(* Logix 5000 project; controller AMCI_3202_generic_sample_RSLogix_V28 vendor 1 type 14 code 92 rev 28.11; software revision 28.00 *)

TASK MainTask (continuous, watchdog 500 ms) : MainProgram

MODULES
   Local : vendor 1 type 14 code 92 (ICP 0, rev 28.11)
      AMCI_3202 : vendor 1 type 0 code 15 (ICP 3, rev 1.1, Output RPI 5 ms)
           Local:3:O.Data[0]   // AMCI 3202 module channel 1 command word
           Local:3:O.Data[8]   // AMCI 3202 module channel 2 command word
           Local:3:I.Data[0].0   // Set when 3202 channel 1 CW motion occurring
           Local:3:I.Data[0].1   // set when 3202 channel 1 CCW motion is occurring
           Local:3:I.Data[0].7   // AMCI 3202 channel 1 move complete bit
           Local:3:I.Data[1]   // AMCI 3202 ch 1 current position data
           Local:3:I.Data[0].10   // AMCI 3202 ch 1 position invalid bit
           Local:3:I.Data[0].13   // Set when AMCI 3202 ch 1 has a configuration error
           Local:3:I.Data[0].31   // AMCI 3202 ch 1 mode bit 1=config mode 0=command mode
           Local:3:I.Data[0].28   // Set when AMCI 3202 ch 1 is disabled
END_MODULES

VAR_GLOBAL   (* controller tags *)
   blend_data_3202_ch1 : DINT[52];
        [13]   // Segment 4 length
        [12]   // Segment 3 Acceleration or Deceleration
        [11]   // Segment 3 speed
        [15]   // Segment 4 Acceleration or Deceleration
        [9]   // Segment 2 Acceleration or Deceleration
        [3]   // Final Segment's Deceleration Value and Type
        [1]   // Number of Segments
        [17]   // Segment 5 speed
        [5]   // Segment 1 speed
        [7]   // Segment 2 length
        [10]   // Segment 3 length
        [14]   // Segment 4 speed
        [16]   // Segment 5 length
        [18]   // Segment 5 Acceleraiton or Deceleration
        [0]   // channel number (1 or 2)
        [2]   // Acceleration Type
        [4]   // Segment 1 length
        [6]   // Segment 1 Acceleration or Deceleration
        [8]   // Segment 2 speed
   blend_data_3202_ch2 : DINT[52];
        [4]   // Segment 1 length
        [14]   // Segment 4 speed
        [6]   // Segment 1 Acceleration or Deceleration
        [17]   // Segment 5 speed
        [11]   // Segment 3 speed
        [15]   // Segment 4 Acceleration or Deceleration
        [1]   // Number of Segments
        [13]   // Segment 4 length
        [3]   // Final Segment's Deceleration Value and Type
        [16]   // Segment 5 length
        [5]   // Segment 1 speed
        [9]   // Segment 2 Acceleration or Deceleration
        [0]   // channel number (1 or 2)
        [7]   // Segment 2 length
        [12]   // Segment 3 Acceleration or Deceleration
        [2]   // Acceleration Type
        [10]   // Segment 3 length
        [18]   // Segment 5 Acceleraiton or Deceleration
        [8]   // Segment 2 speed
   blend_message_3202_ch1 : MESSAGE;
        .DN   // set when blend data has been programmed
        MessageParameters(ServiceCode := 16#004c, LocalElement := blend_data_3202_ch1[0], ...)
   blend_message_3202_ch2 : MESSAGE;
        .DN   // set when blend data has been programmed
        MessageParameters(ServiceCode := 16#004c, LocalElement := blend_data_3202_ch2[0], ...)
   blend_run_3202_ch1 : DINT[8] := ([0] := 4096);
        [0]   // command word to run blend profile CW
   blend_run_3202_ch2 : DINT[8] := ([0] := 4096);
        [0]   // command word to run blend profile CW
   buffered_3202_data : DINT[16];
        [8].0   // set when AMCI 3202 ch 2 CW motion is occurring
        [8].31   // AMCI 3202 ch 2 mode bit 1=config mode 0=command mode
        [0].0   // set when AMCI 3202 ch 1 CW motion is occurring
        [0].1   // set when AMCI 3202 ch 1 CCW motion is occurring
        [0].7   // AMCI 3202 ch 1 move complete bit
        [8].13   // set when AMCI 3202 ch 2 has a configuration error
        [8].1   // set when AMCI 3202 ch 2 CCW motion is occurring
        [0].28   // set when AMCI 3202 ch 1 is disabled
        [8].28   // set when AMCI 3202 ch 2 is disabled
        [0].10   // AMCI 3202 ch 1 position invalid bit
        [0].13   // set when AMCI 3202 ch 1 has a configuration error
        [0].31   // AMCI 3202 ch 1 mode bit 1=config mode 0=command mode
   CCW_manual_move_3202_ch1 : DINT[8] := ([0] := 256, [2] := 2200, [3] := 10000, [4] := 10000);
   CCW_manual_move_3202_ch2 : DINT[8] := ([0] := 256, [2] := 2200, [3] := 10000, [4] := 10000);
   ch1_manual_move_occurring_CCW : BOOL;
   ch1_manual_move_occurring_CW : BOOL;
   ch2_manual_move_occurring_CCW : BOOL;
   ch2_manual_move_occurring_CW2 : BOOL;
   comment : INT;
        .1   // comment coil for version rung
   config_3202_ch1 : DINT[8] := ([0] := -2143419330, [1] := 100);
        [1]   // starting speed
        [0]   // configuration word
   config_3202_ch2 : DINT[8] := ([0] := -2143419330, [1] := 100);
        [1]   // starting speed
        [0]   // configuration word
   CW_manual_move_3202_ch1 : DINT[8] := ([0] := 128, [2] := 1500, [3] := 10000, [4] := 10000);
   CW_manual_move_3202_ch2 : DINT[8] := ([0] := 128, [2] := 1500, [3] := 10000, [4] := 10000);
   Home_CW_3202_ch1 : DINT[8] := ([0] := 32, [2] := 1000, [3] := 10000, [4] := 10000);
   Home_CW_3202_ch2 : DINT[8] := ([0] := 32, [2] := 1000, [3] := 10000, [4] := 10000);
   one_shot_1 : BOOL;
   one_shot_2 : BOOL;
   one_shot_3 : BOOL;
   one_shot_4 : BOOL;
   preset_3202_ch1 : DINT[8] := ([0] := 512);
        [0]   // preset current position command word
   preset_3202_ch2 : DINT[8] := ([0] := 512);
        [0]   // preset current position command word
   Relative_move_3202_ch1 : DINT[8] := ([0] := 2, [1] := 5000, [2] := 2000, [3] := 10000, [4] := 10000);
        [4]   // deceleration in pulses/sec/sec
        [3]   // acceleration in pulses/sec/sec
        [0]   // relative move command word
        [1]   // distance in pulses
        [2]   // speed in pulses/sec
   Relative_move_3202_ch2 : DINT[8] := ([0] := 2, [1] := 5000, [2] := 2000, [3] := 10000, [4] := 10000);
        [3]   // acceleration in pulses/sec/sec
        [4]   // deceleration in pulses/sec/sec
        [0]   // relative move command word
        [1]   // distance in pulses
        [2]   // speed in pulses/sec
   Reset_errors_3202 : DINT[8] := ([0] := 2048);
   run_3202_ch1 : INT;   // 1=Relative move 2=CW Manual Move 3=CCW Manual Move 4=Reset Errors 5=Home CW 6=Preset 7=Program Blend 8=Run Blend CW
   run_3202_ch2 : INT;   // 1=Relative move 2=CW Manual Move 3=CCW Manual Move 4=Reset Errors 5=Home CW 6=Preset 7=Program Blend 8=Run Blend CW
END_VAR

PROGRAM MainProgram   (* main routine MainRoutine *)

ROUTINE channel_1_3202   (* ladder *)
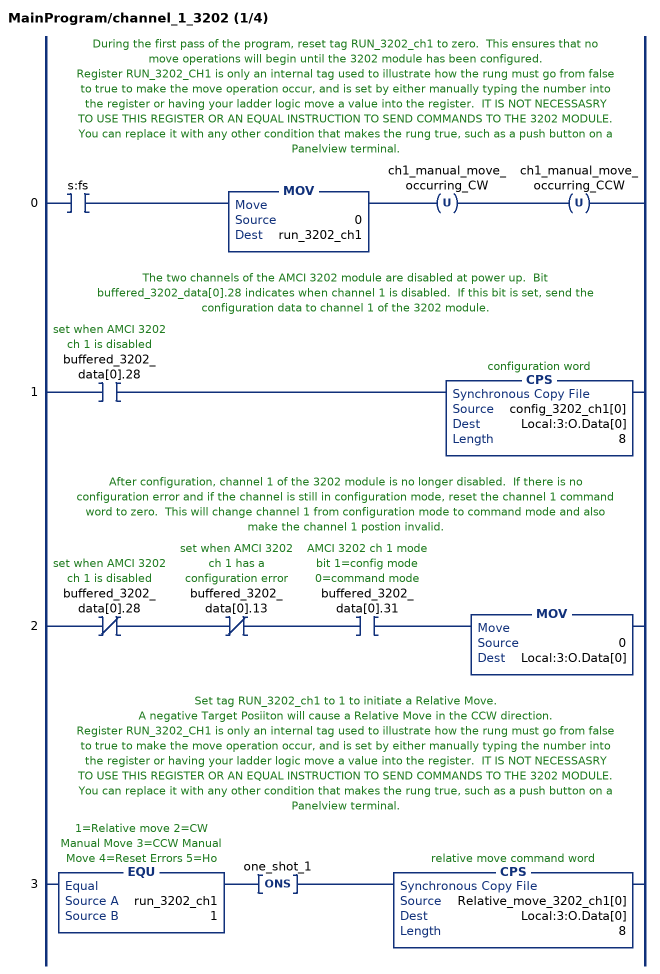
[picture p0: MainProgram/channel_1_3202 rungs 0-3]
   // During the first pass of the program, reset tag RUN_3202_ch1 to zero.  This ensures that no move operations will begin until the 3202 module has been configured.
   // Register RUN_3202_CH1 is only an internal tag used to illustrate how the rung must go from false to true to make the move operation occur, and is set by either manually typing the number into the register or having your ladder logic move a value into the register.  IT IS NOT NECESSASRY TO USE THIS REGISTER OR AN EQUAL INSTRUCTION TO SEND COMMANDS TO THE 3202 MODULE.  You can replace it with any other condition that makes the rung true, such as a push button on a Panelview terminal.
   0: XIC(s:fs)MOV(0,run_3202_ch1)OTU(ch1_manual_move_occurring_CW)OTU(ch1_manual_move_occurring_CCW);
   // The two channels of the AMCI 3202 module are disabled at power up.  Bit buffered_3202_data[0].28 indicates when channel 1 is disabled.  If this bit is set, send the configuration data to channel 1 of the 3202 module.
   1: XIC(buffered_3202_data[0].28)CPS(config_3202_ch1[0],Local:3:O.Data[0],8);
   // After configuration, channel 1 of the 3202 module is no longer disabled.  If there is no configuration error and if the channel is still in configuration mode, reset the channel 1 command word to zero.  This will change channel 1 from configuration mode to command mode and also make the channel 1 postion invalid.
   2: XIO(buffered_3202_data[0].28)XIO(buffered_3202_data[0].13)XIC(buffered_3202_data[0].31)MOV(0,Local:3:O.Data[0]);
   // Set tag RUN_3202_ch1 to 1 to initiate a Relative Move.
   // A negative Target Posiiton will cause a Relative Move in the CCW direction.
   // Register RUN_3202_CH1 is only an internal tag used to illustrate how the rung must go from false to true to make the move operation occur, and is set by either manually typing the number into the register or having your ladder logic move a value into the register.  IT IS NOT NECESSASRY TO USE THIS REGISTER OR AN EQUAL INSTRUCTION TO SEND COMMANDS TO THE 3202 MODULE.  You can replace it with any other condition that makes the rung true, such as a push button on a Panelview terminal.
   3: EQU(run_3202_ch1,1)ONS(one_shot_1)CPS(Relative_move_3202_ch1[0],Local:3:O.Data[0],8);
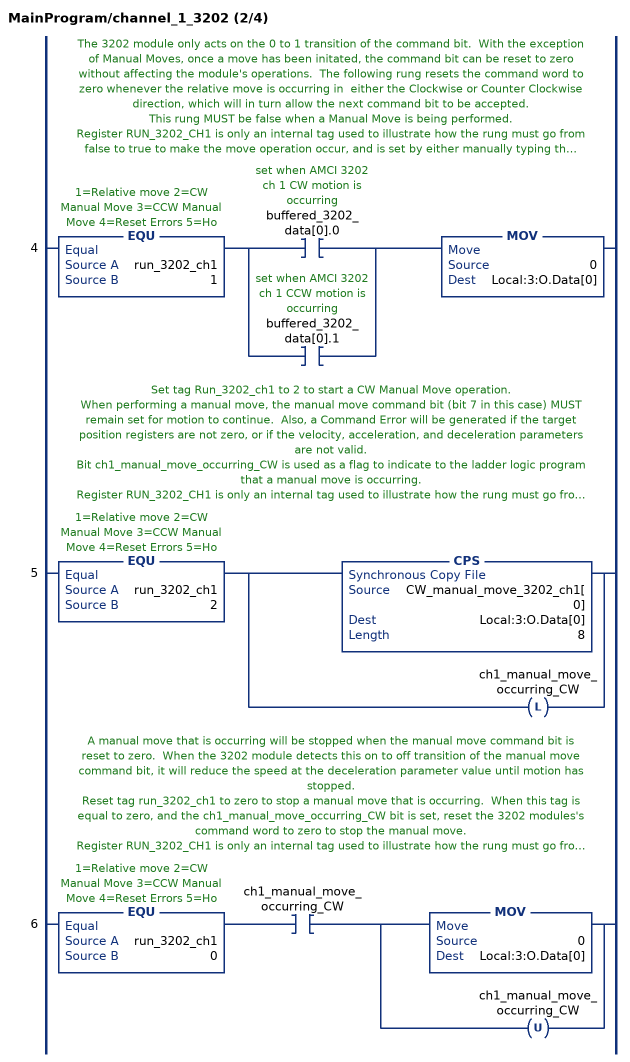
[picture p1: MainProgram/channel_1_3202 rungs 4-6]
   // The 3202 module only acts on the 0 to 1 transition of the command bit.  With the exception of Manual Moves, once a move has been initated, the command bit can be reset to zero without affecting the module's operations.  The following rung resets the command word to zero whenever the relative move is occurring in  either the Clockwise or Counter Clockwise direction, which will in turn allow the next command bit to be accepted.
   // This rung MUST be false when a Manual Move is being performed.
   // Register RUN_3202_CH1 is only an internal tag used to illustrate how the rung must go from false to true to make the move operation occur, and is set by either manually typing the number into the register or having your ladder logic move a value into the register.  IT IS NOT NECESSASRY TO USE THIS REGISTER OR AN EQUAL INSTRUCTION TO SEND COMMANDS TO THE 3202 MODULE.  You can replace it with any other condition that makes the rung true, such as a push button on a Panelview terminal.
   4: EQU(run_3202_ch1,1)[XIC(buffered_3202_data[0].0) ,XIC(buffered_3202_data[0].1) ]MOV(0,Local:3:O.Data[0]);
   // Set tag Run_3202_ch1 to 2 to start a CW Manual Move operation.
   // When performing a manual move, the manual move command bit (bit 7 in this case) MUST remain set for motion to continue.  Also, a Command Error will be generated if the target position registers are not zero, or if the velocity, acceleration, and deceleration parameters are not valid.
   // Bit ch1_manual_move_occurring_CW is used as a flag to indicate to the ladder logic program that a manual move is occurring.
   // Register RUN_3202_CH1 is only an internal tag used to illustrate how the rung must go from false to true to make the move operation occur, and is set by either manually typing the number into the register or having your ladder logic move a value into the register.  IT IS NOT NECESSASRY TO USE THIS REGISTER OR AN EQUAL INSTRUCTION TO SEND COMMANDS TO THE 3202 MODULE.  You can replace it with any other condition that makes the rung true, such as a push button on a Panelview terminal.
   5: EQU(run_3202_ch1,2)[CPS(CW_manual_move_3202_ch1[0],Local:3:O.Data[0],8) ,OTL(ch1_manual_move_occurring_CW) ];
   // A manual move that is occurring will be stopped when the manual move command bit is reset to zero.  When the 3202 module detects this on to off transition of the manual move command bit, it will reduce the speed at the deceleration parameter value until motion has stopped.
   // Reset tag run_3202_ch1 to zero to stop a manual move that is occurring.  When this tag is equal to zero, and the ch1_manual_move_occurring_CW bit is set, reset the 3202 modules's command word to zero to stop the manual move.
   // Register RUN_3202_CH1 is only an internal tag used to illustrate how the rung must go from false to true to make the move operation occur, and is set by either manually typing the number into the register or having your ladder logic move a value into the register.  IT IS NOT NECESSASRY TO USE THIS REGISTER OR AN EQUAL INSTRUCTION TO SEND COMMANDS TO THE 3202 MODULE.  You can replace it with any other condition that makes the rung true, such as a push button on a Panelview terminal.
   6: EQU(run_3202_ch1,0)XIC(ch1_manual_move_occurring_CW)[MOV(0,Local:3:O.Data[0]) ,OTU(ch1_manual_move_occurring_CW) ];
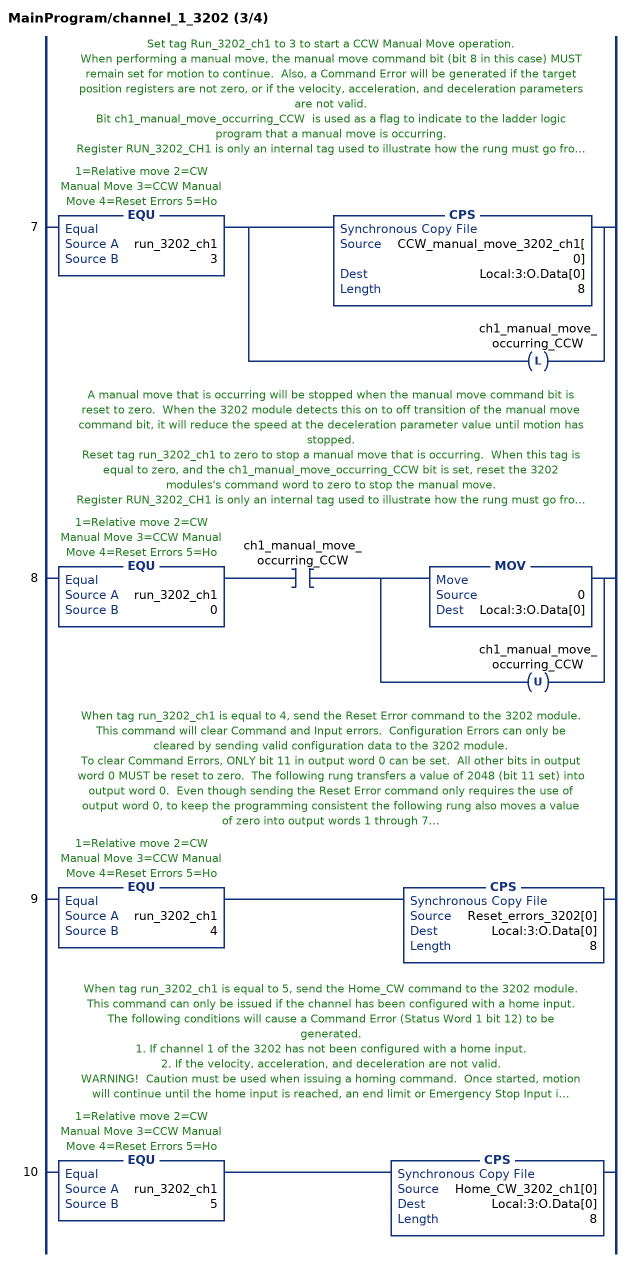
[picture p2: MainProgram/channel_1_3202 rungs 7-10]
   // Set tag Run_3202_ch1 to 3 to start a CCW Manual Move operation.
   // When performing a manual move, the manual move command bit (bit 8 in this case) MUST remain set for motion to continue.  Also, a Command Error will be generated if the target position registers are not zero, or if the velocity, acceleration, and deceleration parameters are not valid.
   // Bit ch1_manual_move_occurring_CCW  is used as a flag to indicate to the ladder logic program that a manual move is occurring.
   // Register RUN_3202_CH1 is only an internal tag used to illustrate how the rung must go from false to true to make the move operation occur, and is set by either manually typing the number into the register or having your ladder logic move a value into the register.  IT IS NOT NECESSASRY TO USE THIS REGISTER OR AN EQUAL INSTRUCTION TO SEND COMMANDS TO THE 3202 MODULE.  You can replace it with any other condition that makes the rung true, such as a push button on a Panelview terminal.
   7: EQU(run_3202_ch1,3)[CPS(CCW_manual_move_3202_ch1[0],Local:3:O.Data[0],8) ,OTL(ch1_manual_move_occurring_CCW) ];
   // A manual move that is occurring will be stopped when the manual move command bit is reset to zero.  When the 3202 module detects this on to off transition of the manual move command bit, it will reduce the speed at the deceleration parameter value until motion has stopped.
   // Reset tag run_3202_ch1 to zero to stop a manual move that is occurring.  When this tag is equal to zero, and the ch1_manual_move_occurring_CCW bit is set, reset the 3202 modules's command word to zero to stop the manual move.
   // Register RUN_3202_CH1 is only an internal tag used to illustrate how the rung must go from false to true to make the move operation occur, and is set by either manually typing the number into the register or having your ladder logic move a value into the register.  IT IS NOT NECESSASRY TO USE THIS REGISTER OR AN EQUAL INSTRUCTION TO SEND COMMANDS TO THE 3202 MODULE.  You can replace it with any other condition that makes the rung true, such as a push button on a Panelview terminal.
   8: EQU(run_3202_ch1,0)XIC(ch1_manual_move_occurring_CCW)[MOV(0,Local:3:O.Data[0]) ,OTU(ch1_manual_move_occurring_CCW) ];
   // When tag run_3202_ch1 is equal to 4, send the Reset Error command to the 3202 module.  This command will clear Command and Input errors.  Configuration Errors can only be cleared by sending valid configuration data to the 3202 module.
   // To clear Command Errors, ONLY bit 11 in output word 0 can be set.  All other bits in output word 0 MUST be reset to zero.  The following rung transfers a value of 2048 (bit 11 set) into output word 0.  Even though sending the Reset Error command only requires the use of output word 0, to keep the programming consistent the following rung also moves a value of zero into output words 1 through 7.
   // Register RUN_3202_CH1 is only an internal tag used to illustrate how the rung must go from false to true to make the move operation occur, and is set by either manually typing the number into the register or having your ladder logic move a value into the register.  IT IS NOT NECESSASRY TO USE THIS REGISTER OR AN EQUAL INSTRUCTION TO SEND COMMANDS TO THE 3202 MODULE.  You can replace it with any other condition that makes the rung true, such as a push button on a Panelview terminal.
   9: EQU(run_3202_ch1,4)CPS(Reset_errors_3202[0],Local:3:O.Data[0],8);
   // When tag run_3202_ch1 is equal to 5, send the Home_CW command to the 3202 module.  This command can only be issued if the channel has been configured with a home input.  The following conditions will cause a Command Error (Status Word 1 bit 12) to be generated.
   // 1. If channel 1 of the 3202 has not been configured with a home input.
   // 2. If the velocity, acceleration, and deceleration are not valid.
   // WARNING!  Caution must be used when issuing a homing command.  Once started, motion will continue until the home input is reached, an end limit or Emergency Stop Input in reached, or the Immediate Stop Command is issued.  Resetting the command word to zero WILL NOT STOP a home operation.
   // Register RUN_3202_CH1 is only an internal tag used to illustrate how the rung must go from false to true to make the move operation occur, and is set by either manually typing the number into the register or having your ladder logic move a value into the register.  IT IS NOT NECESSASRY TO USE THIS REGISTER OR AN EQUAL INSTRUCTION TO SEND COMMANDS TO THE 3202 MODULE.  You can replace it with any other condition that makes the rung true, such as a push button on a Panelview terminal.
   10: EQU(run_3202_ch1,5)CPS(Home_CW_3202_ch1[0],Local:3:O.Data[0],8);
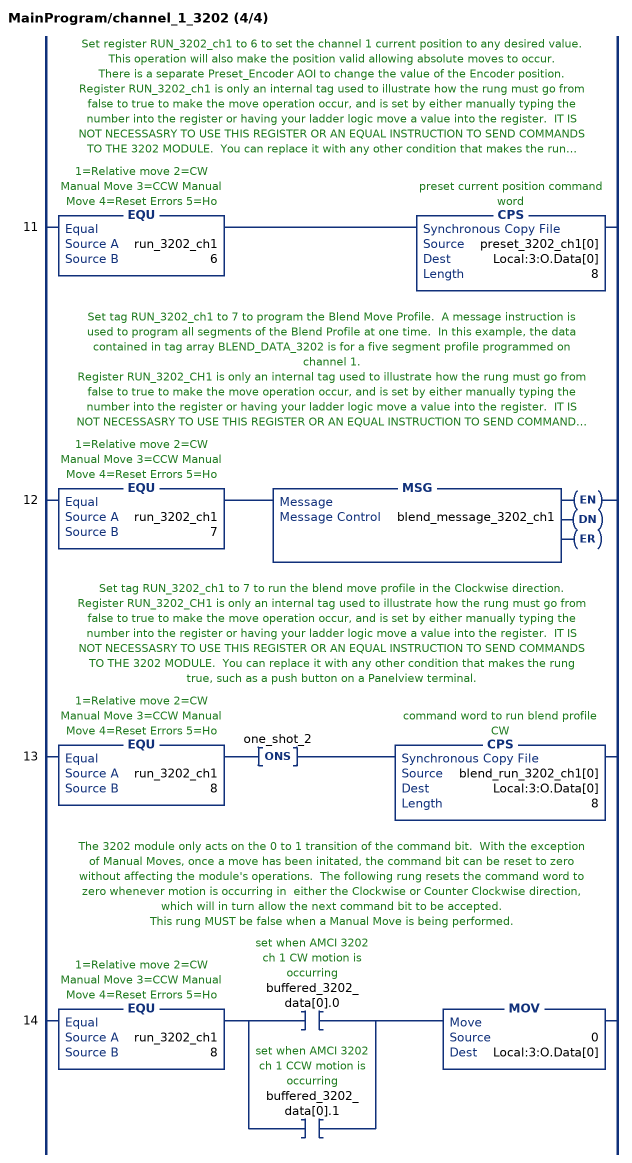
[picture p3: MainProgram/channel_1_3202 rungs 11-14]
   // Set register RUN_3202_ch1 to 6 to set the channel 1 current position to any desired value.  This operation will also make the position valid allowing absolute moves to occur.
   // There is a separate Preset_Encoder AOI to change the value of the Encoder position.
   // Register RUN_3202_ch1 is only an internal tag used to illustrate how the rung must go from false to true to make the move operation occur, and is set by either manually typing the number into the register or having your ladder logic move a value into the register.  IT IS NOT NECESSASRY TO USE THIS REGISTER OR AN EQUAL INSTRUCTION TO SEND COMMANDS TO THE 3202 MODULE.  You can replace it with any other condition that makes the rung true, such as a push button on a Panelview terminal.
   11: EQU(run_3202_ch1,6)CPS(preset_3202_ch1[0],Local:3:O.Data[0],8);
   // Set tag RUN_3202_ch1 to 7 to program the Blend Move Profile.  A message instruction is used to program all segments of the Blend Profile at one time.  In this example, the data contained in tag array BLEND_DATA_3202 is for a five segment profile programmed on channel 1.
   // Register RUN_3202_CH1 is only an internal tag used to illustrate how the rung must go from false to true to make the move operation occur, and is set by either manually typing the number into the register or having your ladder logic move a value into the register.  IT IS NOT NECESSASRY TO USE THIS REGISTER OR AN EQUAL INSTRUCTION TO SEND COMMANDS TO THE 3202 MODULE.  You can replace it with any other condition that makes the rung true, such as a push button on a Panelview terminal.
   12: EQU(run_3202_ch1,7)MSG(blend_message_3202_ch1);
   // Set tag RUN_3202_ch1 to 7 to run the blend move profile in the Clockwise direction.
   // Register RUN_3202_CH1 is only an internal tag used to illustrate how the rung must go from false to true to make the move operation occur, and is set by either manually typing the number into the register or having your ladder logic move a value into the register.  IT IS NOT NECESSASRY TO USE THIS REGISTER OR AN EQUAL INSTRUCTION TO SEND COMMANDS TO THE 3202 MODULE.  You can replace it with any other condition that makes the rung true, such as a push button on a Panelview terminal.
   13: EQU(run_3202_ch1,8)ONS(one_shot_2)CPS(blend_run_3202_ch1[0],Local:3:O.Data[0],8);
   // The 3202 module only acts on the 0 to 1 transition of the command bit.  With the exception of Manual Moves, once a move has been initated, the command bit can be reset to zero without affecting the module's operations.  The following rung resets the command word to zero whenever motion is occurring in  either the Clockwise or Counter Clockwise direction, which will in turn allow the next command bit to be accepted.
   // This rung MUST be false when a Manual Move is being performed.
   14: EQU(run_3202_ch1,8)[XIC(buffered_3202_data[0].0) ,XIC(buffered_3202_data[0].1) ]MOV(0,Local:3:O.Data[0]);
END_ROUTINE

ROUTINE channel_2_3202   (* ladder *)
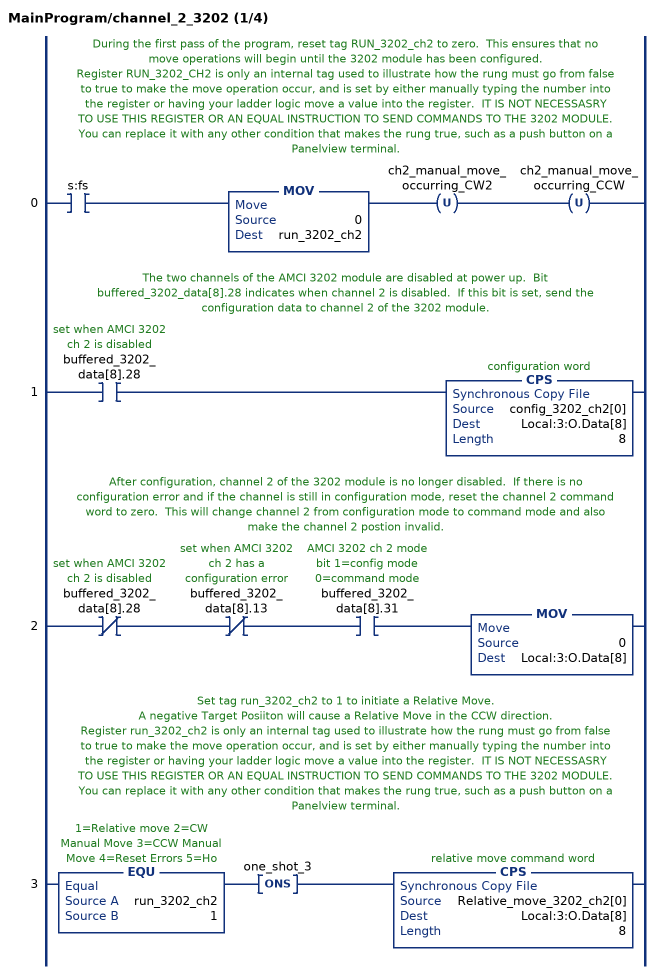
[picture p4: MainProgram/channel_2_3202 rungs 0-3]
   // During the first pass of the program, reset tag RUN_3202_ch2 to zero.  This ensures that no move operations will begin until the 3202 module has been configured.
   // Register RUN_3202_CH2 is only an internal tag used to illustrate how the rung must go from false to true to make the move operation occur, and is set by either manually typing the number into the register or having your ladder logic move a value into the register.  IT IS NOT NECESSASRY TO USE THIS REGISTER OR AN EQUAL INSTRUCTION TO SEND COMMANDS TO THE 3202 MODULE.  You can replace it with any other condition that makes the rung true, such as a push button on a Panelview terminal.
   0: XIC(s:fs)MOV(0,run_3202_ch2)OTU(ch2_manual_move_occurring_CW2)OTU(ch2_manual_move_occurring_CCW);
   // The two channels of the AMCI 3202 module are disabled at power up.  Bit buffered_3202_data[8].28 indicates when channel 2 is disabled.  If this bit is set, send the configuration data to channel 2 of the 3202 module.
   1: XIC(buffered_3202_data[8].28)CPS(config_3202_ch2[0],Local:3:O.Data[8],8);
   // After configuration, channel 2 of the 3202 module is no longer disabled.  If there is no configuration error and if the channel is still in configuration mode, reset the channel 2 command word to zero.  This will change channel 2 from configuration mode to command mode and also make the channel 2 postion invalid.
   2: XIO(buffered_3202_data[8].28)XIO(buffered_3202_data[8].13)XIC(buffered_3202_data[8].31)MOV(0,Local:3:O.Data[8]);
   // Set tag run_3202_ch2 to 1 to initiate a Relative Move.
   // A negative Target Posiiton will cause a Relative Move in the CCW direction.
   // Register run_3202_ch2 is only an internal tag used to illustrate how the rung must go from false to true to make the move operation occur, and is set by either manually typing the number into the register or having your ladder logic move a value into the register.  IT IS NOT NECESSASRY TO USE THIS REGISTER OR AN EQUAL INSTRUCTION TO SEND COMMANDS TO THE 3202 MODULE.  You can replace it with any other condition that makes the rung true, such as a push button on a Panelview terminal.
   3: EQU(run_3202_ch2,1)ONS(one_shot_3)CPS(Relative_move_3202_ch2[0],Local:3:O.Data[8],8);
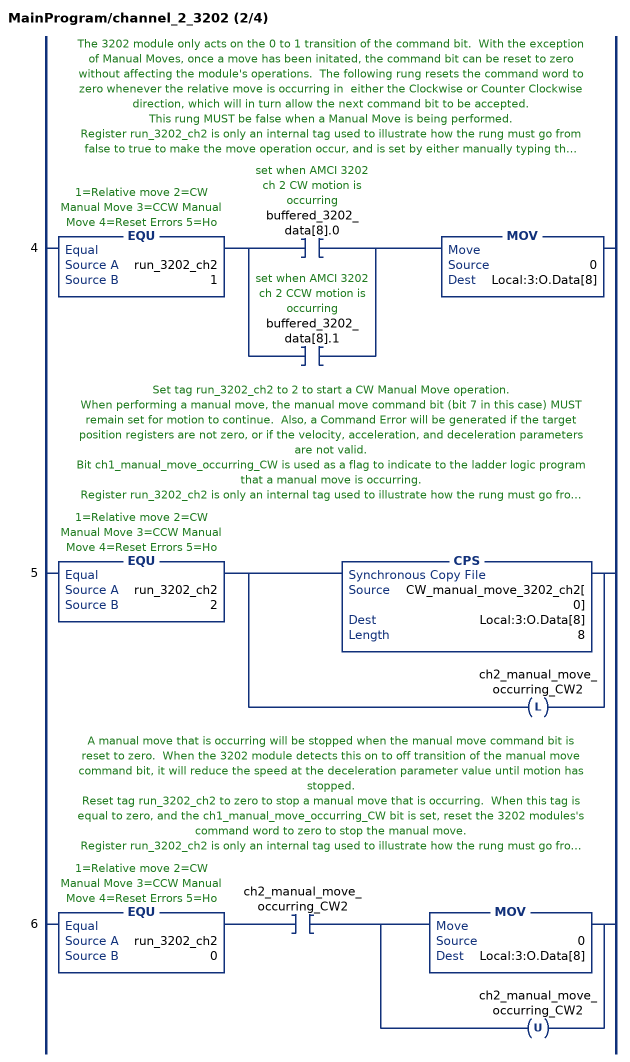
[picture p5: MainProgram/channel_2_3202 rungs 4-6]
   // The 3202 module only acts on the 0 to 1 transition of the command bit.  With the exception of Manual Moves, once a move has been initated, the command bit can be reset to zero without affecting the module's operations.  The following rung resets the command word to zero whenever the relative move is occurring in  either the Clockwise or Counter Clockwise direction, which will in turn allow the next command bit to be accepted.
   // This rung MUST be false when a Manual Move is being performed.
   // Register run_3202_ch2 is only an internal tag used to illustrate how the rung must go from false to true to make the move operation occur, and is set by either manually typing the number into the register or having your ladder logic move a value into the register.  IT IS NOT NECESSASRY TO USE THIS REGISTER OR AN EQUAL INSTRUCTION TO SEND COMMANDS TO THE 3202 MODULE.  You can replace it with any other condition that makes the rung true, such as a push button on a Panelview terminal.
   4: EQU(run_3202_ch2,1)[XIC(buffered_3202_data[8].0) ,XIC(buffered_3202_data[8].1) ]MOV(0,Local:3:O.Data[8]);
   // Set tag run_3202_ch2 to 2 to start a CW Manual Move operation.
   // When performing a manual move, the manual move command bit (bit 7 in this case) MUST remain set for motion to continue.  Also, a Command Error will be generated if the target position registers are not zero, or if the velocity, acceleration, and deceleration parameters are not valid.
   // Bit ch1_manual_move_occurring_CW is used as a flag to indicate to the ladder logic program that a manual move is occurring.
   // Register run_3202_ch2 is only an internal tag used to illustrate how the rung must go from false to true to make the move operation occur, and is set by either manually typing the number into the register or having your ladder logic move a value into the register.  IT IS NOT NECESSASRY TO USE THIS REGISTER OR AN EQUAL INSTRUCTION TO SEND COMMANDS TO THE 3202 MODULE.  You can replace it with any other condition that makes the rung true, such as a push button on a Panelview terminal.
   5: EQU(run_3202_ch2,2)[CPS(CW_manual_move_3202_ch2[0],Local:3:O.Data[8],8) ,OTL(ch2_manual_move_occurring_CW2) ];
   // A manual move that is occurring will be stopped when the manual move command bit is reset to zero.  When the 3202 module detects this on to off transition of the manual move command bit, it will reduce the speed at the deceleration parameter value until motion has stopped.
   // Reset tag run_3202_ch2 to zero to stop a manual move that is occurring.  When this tag is equal to zero, and the ch1_manual_move_occurring_CW bit is set, reset the 3202 modules's command word to zero to stop the manual move.
   // Register run_3202_ch2 is only an internal tag used to illustrate how the rung must go from false to true to make the move operation occur, and is set by either manually typing the number into the register or having your ladder logic move a value into the register.  IT IS NOT NECESSASRY TO USE THIS REGISTER OR AN EQUAL INSTRUCTION TO SEND COMMANDS TO THE 3202 MODULE.  You can replace it with any other condition that makes the rung true, such as a push button on a Panelview terminal.
   6: EQU(run_3202_ch2,0)XIC(ch2_manual_move_occurring_CW2)[MOV(0,Local:3:O.Data[8]) ,OTU(ch2_manual_move_occurring_CW2) ];
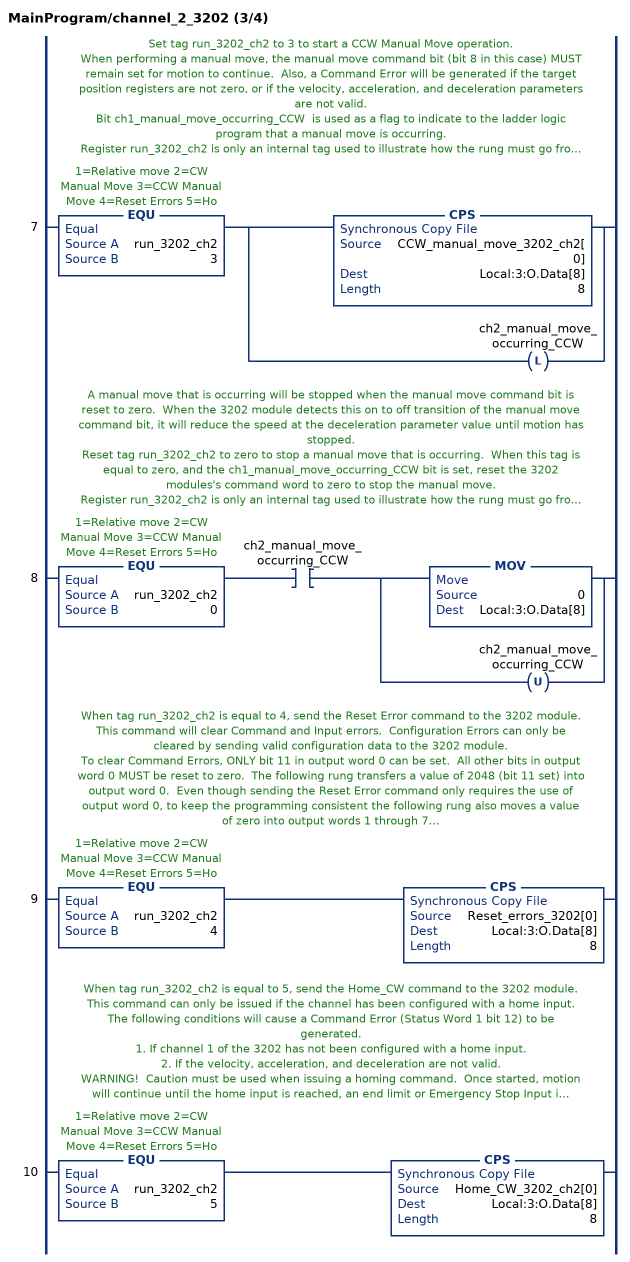
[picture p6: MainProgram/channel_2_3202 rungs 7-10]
   // Set tag run_3202_ch2 to 3 to start a CCW Manual Move operation.
   // When performing a manual move, the manual move command bit (bit 8 in this case) MUST remain set for motion to continue.  Also, a Command Error will be generated if the target position registers are not zero, or if the velocity, acceleration, and deceleration parameters are not valid.
   // Bit ch1_manual_move_occurring_CCW  is used as a flag to indicate to the ladder logic program that a manual move is occurring.
   // Register run_3202_ch2 is only an internal tag used to illustrate how the rung must go from false to true to make the move operation occur, and is set by either manually typing the number into the register or having your ladder logic move a value into the register.  IT IS NOT NECESSASRY TO USE THIS REGISTER OR AN EQUAL INSTRUCTION TO SEND COMMANDS TO THE 3202 MODULE.  You can replace it with any other condition that makes the rung true, such as a push button on a Panelview terminal.
   7: EQU(run_3202_ch2,3)[CPS(CCW_manual_move_3202_ch2[0],Local:3:O.Data[8],8) ,OTL(ch2_manual_move_occurring_CCW) ];
   // A manual move that is occurring will be stopped when the manual move command bit is reset to zero.  When the 3202 module detects this on to off transition of the manual move command bit, it will reduce the speed at the deceleration parameter value until motion has stopped.
   // Reset tag run_3202_ch2 to zero to stop a manual move that is occurring.  When this tag is equal to zero, and the ch1_manual_move_occurring_CCW bit is set, reset the 3202 modules's command word to zero to stop the manual move.
   // Register run_3202_ch2 is only an internal tag used to illustrate how the rung must go from false to true to make the move operation occur, and is set by either manually typing the number into the register or having your ladder logic move a value into the register.  IT IS NOT NECESSASRY TO USE THIS REGISTER OR AN EQUAL INSTRUCTION TO SEND COMMANDS TO THE 3202 MODULE.  You can replace it with any other condition that makes the rung true, such as a push button on a Panelview terminal.
   8: EQU(run_3202_ch2,0)XIC(ch2_manual_move_occurring_CCW)[MOV(0,Local:3:O.Data[8]) ,OTU(ch2_manual_move_occurring_CCW) ];
   // When tag run_3202_ch2 is equal to 4, send the Reset Error command to the 3202 module.  This command will clear Command and Input errors.  Configuration Errors can only be cleared by sending valid configuration data to the 3202 module.
   // To clear Command Errors, ONLY bit 11 in output word 0 can be set.  All other bits in output word 0 MUST be reset to zero.  The following rung transfers a value of 2048 (bit 11 set) into output word 0.  Even though sending the Reset Error command only requires the use of output word 0, to keep the programming consistent the following rung also moves a value of zero into output words 1 through 7.
   // Register run_3202_ch2 is only an internal tag used to illustrate how the rung must go from false to true to make the move operation occur, and is set by either manually typing the number into the register or having your ladder logic move a value into the register.  IT IS NOT NECESSASRY TO USE THIS REGISTER OR AN EQUAL INSTRUCTION TO SEND COMMANDS TO THE 3202 MODULE.  You can replace it with any other condition that makes the rung true, such as a push button on a Panelview terminal.
   9: EQU(run_3202_ch2,4)CPS(Reset_errors_3202[0],Local:3:O.Data[8],8);
   // When tag run_3202_ch2 is equal to 5, send the Home_CW command to the 3202 module.  This command can only be issued if the channel has been configured with a home input.  The following conditions will cause a Command Error (Status Word 1 bit 12) to be generated.
   // 1. If channel 1 of the 3202 has not been configured with a home input.
   // 2. If the velocity, acceleration, and deceleration are not valid.
   // WARNING!  Caution must be used when issuing a homing command.  Once started, motion will continue until the home input is reached, an end limit or Emergency Stop Input in reached, or the Immediate Stop Command is issued.  Resetting the command word to zero WILL NOT STOP a home operation.
   // Register run_3202_ch2 is only an internal tag used to illustrate how the rung must go from false to true to make the move operation occur, and is set by either manually typing the number into the register or having your ladder logic move a value into the register.  IT IS NOT NECESSASRY TO USE THIS REGISTER OR AN EQUAL INSTRUCTION TO SEND COMMANDS TO THE 3202 MODULE.  You can replace it with any other condition that makes the rung true, such as a push button on a Panelview terminal.
   10: EQU(run_3202_ch2,5)CPS(Home_CW_3202_ch2[0],Local:3:O.Data[8],8);
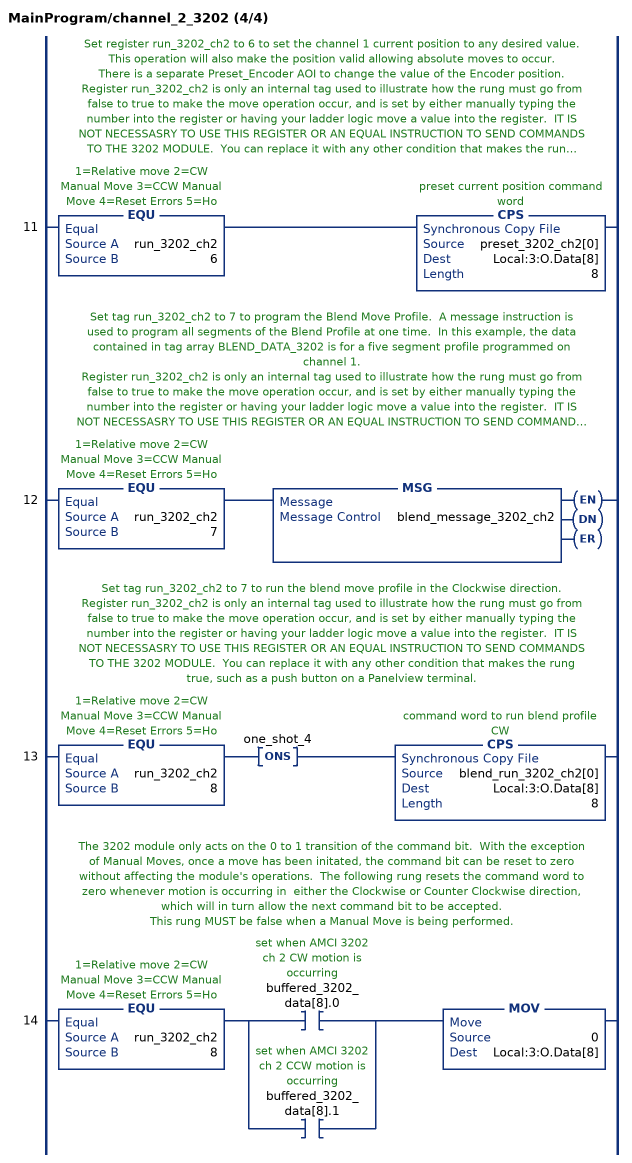
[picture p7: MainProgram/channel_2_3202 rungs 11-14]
   // Set register run_3202_ch2 to 6 to set the channel 1 current position to any desired value.  This operation will also make the position valid allowing absolute moves to occur.
   // There is a separate Preset_Encoder AOI to change the value of the Encoder position.
   // Register run_3202_ch2 is only an internal tag used to illustrate how the rung must go from false to true to make the move operation occur, and is set by either manually typing the number into the register or having your ladder logic move a value into the register.  IT IS NOT NECESSASRY TO USE THIS REGISTER OR AN EQUAL INSTRUCTION TO SEND COMMANDS TO THE 3202 MODULE.  You can replace it with any other condition that makes the rung true, such as a push button on a Panelview terminal.
   11: EQU(run_3202_ch2,6)CPS(preset_3202_ch2[0],Local:3:O.Data[8],8);
   // Set tag run_3202_ch2 to 7 to program the Blend Move Profile.  A message instruction is used to program all segments of the Blend Profile at one time.  In this example, the data contained in tag array BLEND_DATA_3202 is for a five segment profile programmed on channel 1.
   // Register run_3202_ch2 is only an internal tag used to illustrate how the rung must go from false to true to make the move operation occur, and is set by either manually typing the number into the register or having your ladder logic move a value into the register.  IT IS NOT NECESSASRY TO USE THIS REGISTER OR AN EQUAL INSTRUCTION TO SEND COMMANDS TO THE 3202 MODULE.  You can replace it with any other condition that makes the rung true, such as a push button on a Panelview terminal.
   12: EQU(run_3202_ch2,7)MSG(blend_message_3202_ch2);
   // Set tag run_3202_ch2 to 7 to run the blend move profile in the Clockwise direction.
   // Register run_3202_ch2 is only an internal tag used to illustrate how the rung must go from false to true to make the move operation occur, and is set by either manually typing the number into the register or having your ladder logic move a value into the register.  IT IS NOT NECESSASRY TO USE THIS REGISTER OR AN EQUAL INSTRUCTION TO SEND COMMANDS TO THE 3202 MODULE.  You can replace it with any other condition that makes the rung true, such as a push button on a Panelview terminal.
   13: EQU(run_3202_ch2,8)ONS(one_shot_4)CPS(blend_run_3202_ch2[0],Local:3:O.Data[8],8);
   // The 3202 module only acts on the 0 to 1 transition of the command bit.  With the exception of Manual Moves, once a move has been initated, the command bit can be reset to zero without affecting the module's operations.  The following rung resets the command word to zero whenever motion is occurring in  either the Clockwise or Counter Clockwise direction, which will in turn allow the next command bit to be accepted.
   // This rung MUST be false when a Manual Move is being performed.
   14: EQU(run_3202_ch2,8)[XIC(buffered_3202_data[8].0) ,XIC(buffered_3202_data[8].1) ]MOV(0,Local:3:O.Data[8]);
END_ROUTINE

ROUTINE MainRoutine   (* ladder *)
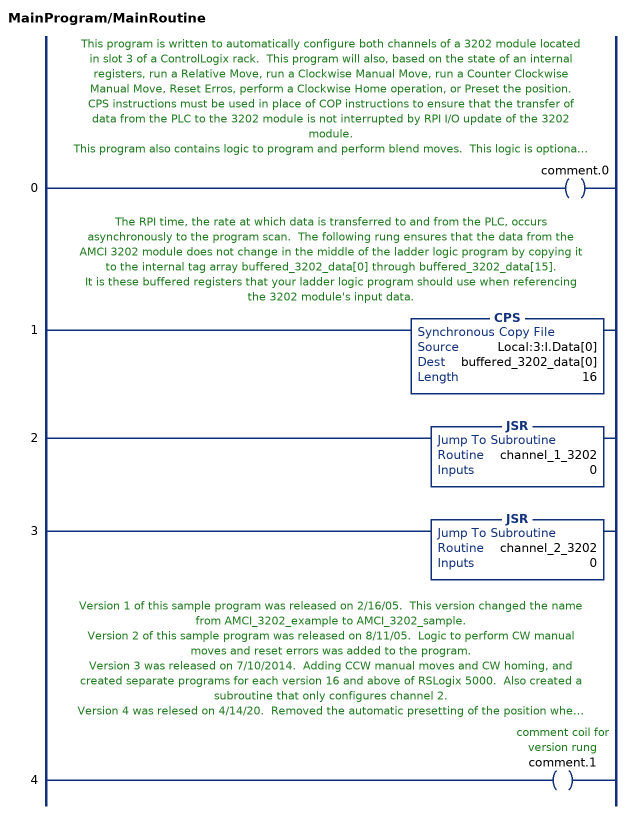
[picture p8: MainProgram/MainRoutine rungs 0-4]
   // This program is written to automatically configure both channels of a 3202 module located in slot 3 of a ControlLogix rack.  This program will also, based on the state of an internal registers, run a Relative Move, run a Clockwise Manual Move, run a Counter Clockwise Manual Move, Reset Erros, perform a Clockwise Home operation, or Preset the position.
   // CPS instructions must be used in place of COP instructions to ensure that the transfer of data from the PLC to the 3202 module is not interrupted by RPI I/O update of the 3202 module.
   // This program also contains logic to program and perform blend moves.  This logic is optional and if not needed, can be deleted or ignored.
   // Registers RUN_3202_channel_1 and RUN_3202_channel_2  are only internal tags used to illustrate how the rung must go from false to true to make the move operation occur, and is set by either manually typing the number into the register or having your ladder logic move a value into the register.  IT IS NOT NECESSASRY TO USE these REGISTER OR AN EQUAL INSTRUCTION TO SEND COMMANDS TO THE 3202 MODULE.  You can replace it with any other condition that makes the rung true, such as a push button on a Panelview terminal.
   0: OTE(comment.0);
   // The RPI time, the rate at which data is transferred to and from the PLC, occurs asynchronously to the program scan.  The following rung ensures that the data from the AMCI 3202 module does not change in the middle of the ladder logic program by copying it to the internal tag array buffered_3202_data[0] through buffered_3202_data[15].
   // It is these buffered registers that your ladder logic program should use when referencing the 3202 module's input data.
   1: CPS(Local:3:I.Data[0],buffered_3202_data[0],16);
   2: JSR(channel_1_3202,0);
   3: JSR(channel_2_3202,0);
   // Version 1 of this sample program was released on 2/16/05.  This version changed the name from AMCI_3202_example to AMCI_3202_sample.
   // Version 2 of this sample program was released on 8/11/05.  Logic to perform CW manual moves and reset errors was added to the program.
   // Version 3 was released on 7/10/2014.  Adding CCW manual moves and CW homing, and created separate programs for each version 16 and above of RSLogix 5000.  Also created a subroutine that only configures channel 2.
   // Version 4 was relesed on 4/14/20.  Removed the automatic presetting of the position when it is invalid and the repetitive relative move.   Also created all of the logic for channel 2.
   4: OTE(comment.1);
END_ROUTINE
END_PROGRAM
